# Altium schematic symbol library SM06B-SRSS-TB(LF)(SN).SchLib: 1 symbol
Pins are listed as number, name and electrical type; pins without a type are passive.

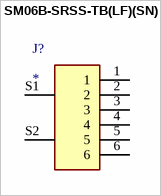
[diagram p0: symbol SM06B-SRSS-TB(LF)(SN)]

## SM06B-SRSS-TB(LF)(SN)
designator J?
Connector Header Surface Mount, Right Angle 6 position 0.039 (1.00mm); MF: JST Sales; MP: SM06B-SRSS-TB(LF)(SN)
footprint JST_SM06B-SRSS-TB(LF)(SN)
pins: 1, 2, 3, 4, 5, 6, S1 SHIELD, S2 SHIELD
